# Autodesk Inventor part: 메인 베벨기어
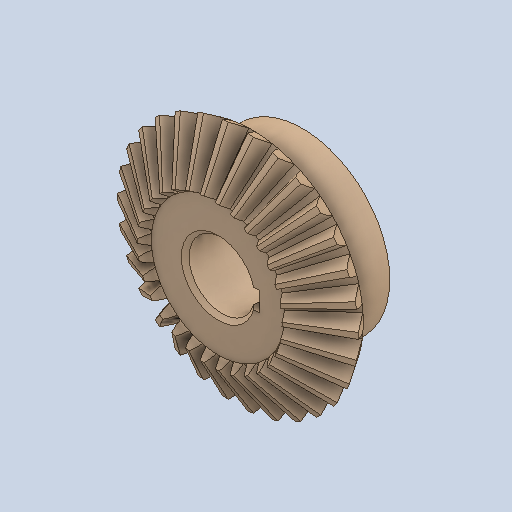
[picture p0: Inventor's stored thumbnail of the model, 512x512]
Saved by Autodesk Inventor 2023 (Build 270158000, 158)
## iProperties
Created: 2025-04
Part Number: 메인 베벨기어
Material: 강철, 탄소
Document SubType Name: Modeling
Designer: User
Density: 7.87 g/cm^3
Appearance: 기본값
Author: jhkim
Revision Number: 1
Sending System: Autodesk Inventor 2026
Preprocessor: ST-DEVELOPER v20.1
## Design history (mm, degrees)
feature "Solid1"
node "솔리드1"
